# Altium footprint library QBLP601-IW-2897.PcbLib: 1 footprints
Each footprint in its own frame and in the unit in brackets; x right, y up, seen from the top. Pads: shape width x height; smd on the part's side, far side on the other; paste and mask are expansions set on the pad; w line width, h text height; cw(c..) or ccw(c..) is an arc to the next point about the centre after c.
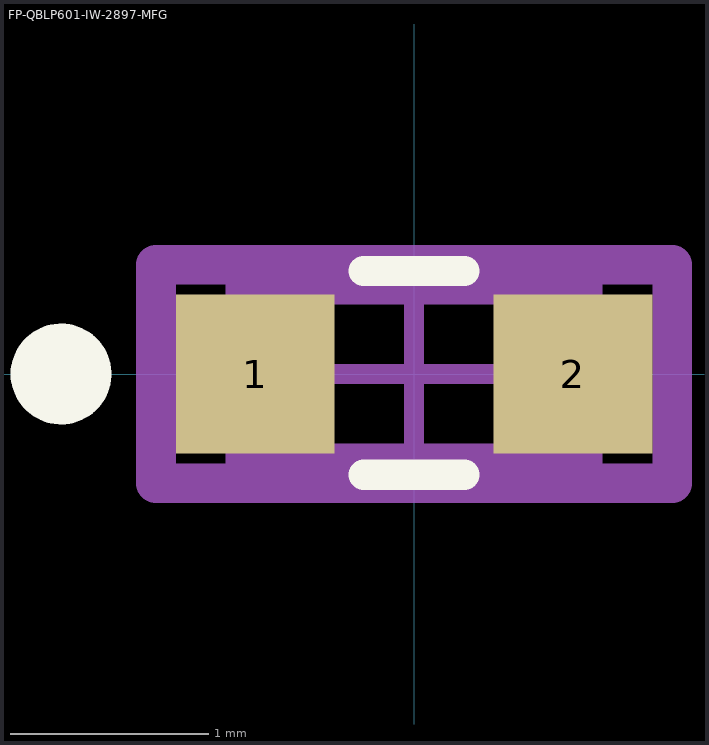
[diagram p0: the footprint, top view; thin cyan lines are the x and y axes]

## FP-QBLP601-IW-2897-MFG [mm]
pads (2):
  rect 0.8x0.8 smd paste+0 mask+0: 1(-0.8,0) 2(0.8,0)
Top Overlay:
  circle w0.254: c-1.778,0 r0.127
  lines w0.152: -0.254,-0.508 0.254,-0.508 ; -0.254,0.519 0.254,0.519
Mechanical 5:
  lines w0.2: -1.3,-0.55 1.3,-0.55 1.3,0.55 -1.3,0.55 -1.3,-0.55
  text ".Designator" at 0,0 h1
Mechanical 13:
  lines w0.2: -0.85,-0.45 0.85,-0.45 0.85,0.45 -0.85,0.45 -0.85,-0.45
Mechanical 15:
  lines w0.2: -1.3,-0.55 1.3,-0.55 1.3,0.55 -1.3,0.55 -1.3,-0.55
Mechanical 16:
  lines w0.1: -0.5,0 0.5,0 ; 0,-0.5 0,0.5
3D body "QBLP601_MONO(V2).step": height 0.6, standoff 0, extent -0.8,-0.4 0.8,0.4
